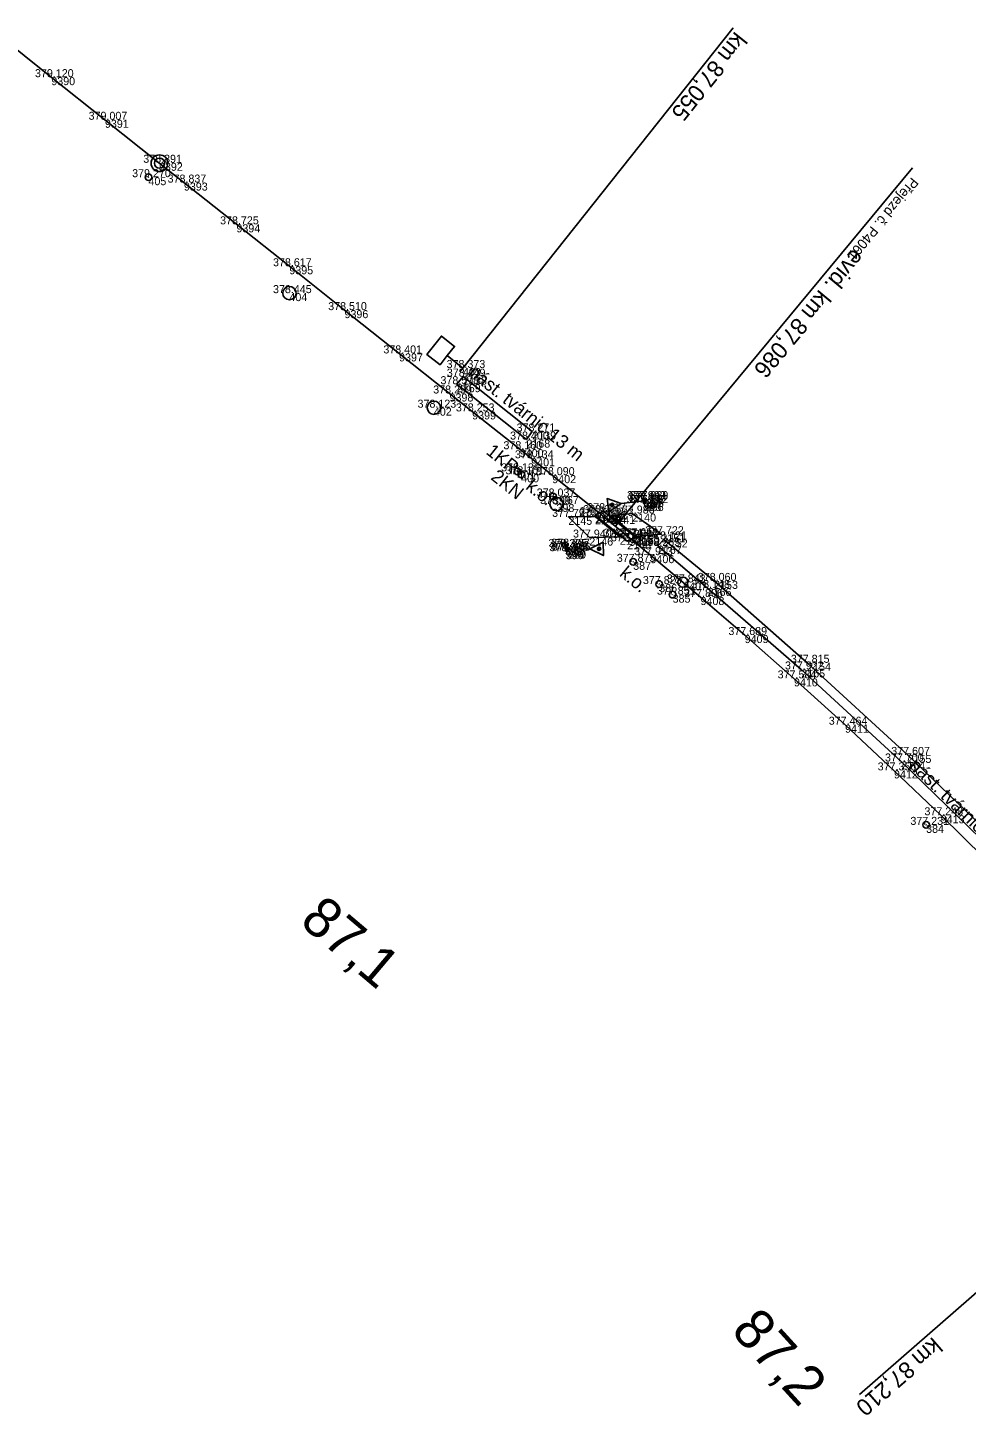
# Model space of a CAD drawing. Extents: x -599511 to -595511, y -1067427 to -1062061.
# Drawn here: x -596866.3 to -596725.5, y -1065469.6 to -1065261.5 of the extents above; entities that cross this region are included whole.
import ezdxf

# ---------------------------------------------------------------- set-up
doc = ezdxf.new("R2010")
doc.units = 0
for name, color, linetype in [('Vrstva 1', 7, 'Continuous'), ('Vrstva 12', 7, 'Continuous'), ('Vrstva 14', 7, 'Continuous'), ('Vrstva 27', 7, 'Continuous'), ('Vrstva 4', 7, 'Continuous'), ('Vrstva 43', 7, 'Continuous'), ('Vrstva 50', 7, 'Continuous'), ('Vrstva 60', 7, 'Continuous'), ('Vrstva 61', 7, 'Continuous'), ('Vrstva 7', 7, 'Continuous')]:
    doc.layers.add(name, color=color, linetype=linetype)

msp = doc.modelspace()

# ---------------------------------------------------------------- linework, layer by layer
at = {"layer": 'Vrstva 1'}
msp.add_lwpolyline([(-596870.95, -1065262.4), (-596862.77, -1065268.89), (-596854.72, -1065275.28), (-596846.61, -1065281.73), (-596842.87, -1065284.7), (-596834.99, -1065290.96), (-596827.05, -1065297.25), (-596818.77, -1065303.83), (-596810.58, -1065310.32), (-596803.01, -1065316.33), (-596799.61, -1065319.02), (-596792.47, -1065324.69), (-596790.75, -1065326.05), (-596787.59, -1065328.58), (-596780.52, -1065334.28), (-596780.05, -1065334.66), (-596775.99, -1065337.98), (-596772.85, -1065340.58), (-596767.94, -1065344.67), (-596765.34, -1065346.86), (-596758.71, -1065352.56), (-596751.32, -1065359.06), (-596743.65, -1065366.01), (-596736.31, -1065372.86), (-596729.29, -1065379.59), (-596722.75, -1065386.03)], dxfattribs=at)
at = {"layer": 'Vrstva 12'}
for points in [[(-596773.92, -1065332.17), (-596773.93, -1065332.76), (-596773.55, -1065332.77), (-596773.53, -1065332.18)], [(-596785.69, -1065339.35), (-596785.3, -1065339.31), (-596785.19, -1065339.89), (-596785.57, -1065339.98)]]:
    msp.add_lwpolyline(points, close=True, dxfattribs=at)
at = {"layer": 'Vrstva 14'}
msp.add_lwpolyline([(-596790.59, -1065322.03), (-596791.47, -1065323.24), (-596801.91, -1065314.94), (-596800.97, -1065313.8)], close=True, dxfattribs=at)
msp.add_lwpolyline([(-596688.36, -1065420.16), (-596688.18, -1065420.03), (-596687.53, -1065420.8), (-596687.34, -1065420.62), (-596688.01, -1065419.84), (-596687.33, -1065419.23), (-596705.98, -1065398.67), (-596706.41, -1065398.26), (-596706.92, -1065397.78), (-596720.57, -1065383.66), (-596734.27, -1065370.54), (-596749.34, -1065356.72), (-596763.3, -1065344.44), (-596770.84, -1065338.22), (-596771.74, -1065339.2), (-596764.28, -1065345.51), (-596750.22, -1065357.72), (-596735.21, -1065371.52), (-596721.61, -1065384.72), (-596707.91, -1065398.76), (-596707.49, -1065399.19), (-596707.13, -1065399.59), (-596688.36, -1065420.16)], dxfattribs=at)
at = {"layer": 'Vrstva 27'}
for p, q in [((-596792.86, -1065327.97), (-596792.78, -1065328.04)), ((-596792.3, -1065328.42), (-596792.22, -1065328.48)), ((-596787.51, -1065331.75), (-596787.44, -1065331.81)), ((-596775.49, -1065341.54), (-596775.41, -1065341.61))]:
    msp.add_line(p, q, dxfattribs=at)
for centre in [(-596792.82, -1065328.01), (-596792.26, -1065328.45), (-596787.48, -1065331.78), (-596775.45, -1065341.58)]:
    msp.add_circle(centre, 0.5, dxfattribs=at)
at = {"layer": 'Vrstva 4'}
for p, q in [((-596778.12, -1065336.23), (-596733.55, -1065282.5)), ((-596773.7, -1065333.21), (-596773.89, -1065331.66)), ((-596778.4, -1065333.2), (-596778.79, -1065332.9)), ((-596785.42, -1065338.91), (-596785.41, -1065340.46)), ((-596780.74, -1065339.43), (-596780.4, -1065339.78))]:
    msp.add_line(p, q, dxfattribs=at)
for points in [[(-596773.79, -1065332.43), (-596777.25, -1065332.85), (-596779.12, -1065334.08), (-596779.36, -1065332.09), (-596777.25, -1065332.85)], [(-596785.41, -1065339.69), (-596781.94, -1065339.65), (-596779.94, -1065338.64), (-596779.91, -1065340.64), (-596781.94, -1065339.65)]]:
    msp.add_lwpolyline(points, dxfattribs=at)
for points in [[(-596777.45, -1065337.81), (-596781.17, -1065334.77), (-596785.17, -1065334.83), (-596782.03, -1065337.94)], [(-596775.07, -1065337.93), (-596779.89, -1065333.98), (-596781.14, -1065334.59), (-596776.34, -1065338.5)], [(-596771.21, -1065337.44), (-596775.59, -1065334.34), (-596778.73, -1065334.7), (-596775.04, -1065337.74)]]:
    msp.add_lwpolyline(points, close=True, dxfattribs=at)
for centre in [(-596778.59, -1065333.05), (-596780.57, -1065339.61)]:
    msp.add_circle(centre, 0.248, dxfattribs=at)
at = {"layer": 'Vrstva 43'}
for centre in [(-596827.04, -1065301.28), (-596805.36, -1065318.46), (-596786.96, -1065332.91)]:
    msp.add_circle(centre, 1, dxfattribs=at)
at = {"layer": 'Vrstva 50'}
for p, q in [((-596771.58, -1065344.88), (-596771.5, -1065344.94)), ((-596731.53, -1065381), (-596731.45, -1065381.07))]:
    msp.add_line(p, q, dxfattribs=at)
for centre in [(-596771.54, -1065344.91), (-596731.49, -1065381.03)]:
    msp.add_circle(centre, 0.5, dxfattribs=at)
at = {"layer": 'Vrstva 60'}
for p, q in [((-596862.77, -1065268.89), (-596862.77, -1065268.89)), ((-596854.72, -1065275.28), (-596854.72, -1065275.28)), ((-596846.61, -1065281.73), (-596846.61, -1065281.73)), ((-596848.19, -1065283.89), (-596848.19, -1065283.89)), ((-596842.87, -1065284.7), (-596842.87, -1065284.7)), ((-596834.99, -1065290.96), (-596834.99, -1065290.96)), ((-596827.05, -1065297.25), (-596827.05, -1065297.25)), ((-596827.04, -1065301.28), (-596827.04, -1065301.28)), ((-596818.77, -1065303.83), (-596818.77, -1065303.83)), ((-596810.58, -1065310.32), (-596810.58, -1065310.32)), ((-596801, -1065312.51), (-596801, -1065312.51)), ((-596800.97, -1065313.8), (-596800.97, -1065313.8)), ((-596801.91, -1065314.94), (-596801.91, -1065314.94)), ((-596803.01, -1065316.33), (-596803.01, -1065316.33)), ((-596805.36, -1065318.46), (-596805.36, -1065318.46)), ((-596799.61, -1065319.02), (-596799.61, -1065319.02)), ((-596790.59, -1065322.03), (-596790.59, -1065322.03)), ((-596791.47, -1065323.24), (-596791.47, -1065323.24)), ((-596792.47, -1065324.69), (-596792.47, -1065324.69)), ((-596790.75, -1065326.05), (-596790.75, -1065326.05)), ((-596792.82, -1065328.01), (-596792.82, -1065328.01)), ((-596792.26, -1065328.45), (-596792.26, -1065328.45)), ((-596787.59, -1065328.58), (-596787.59, -1065328.58)), ((-596787.48, -1065331.78), (-596787.48, -1065331.78)), ((-596773.93, -1065332.76), (-596773.93, -1065332.76)), ((-596773.92, -1065332.17), (-596773.92, -1065332.17)), ((-596773.79, -1065332.43), (-596773.79, -1065332.43)), ((-596773.55, -1065332.77), (-596773.55, -1065332.77)), ((-596773.53, -1065332.18), (-596773.53, -1065332.18)), ((-596786.96, -1065332.91), (-596786.96, -1065332.91)), ((-596785.17, -1065334.83), (-596785.17, -1065334.83)), ((-596781.17, -1065334.77), (-596781.17, -1065334.77)), ((-596781.14, -1065334.59), (-596781.14, -1065334.59)), ((-596780.52, -1065334.28), (-596780.52, -1065334.28)), ((-596780.05, -1065334.66), (-596780.05, -1065334.66)), ((-596779.89, -1065333.98), (-596779.89, -1065333.98)), ((-596778.73, -1065334.7), (-596778.73, -1065334.7)), ((-596775.59, -1065334.34), (-596775.59, -1065334.34)), ((-596782.03, -1065337.94), (-596782.03, -1065337.94)), ((-596777.45, -1065337.81), (-596777.45, -1065337.81)), ((-596776.34, -1065338.5), (-596776.34, -1065338.5)), ((-596775.99, -1065337.98), (-596775.99, -1065337.98)), ((-596775.07, -1065337.93), (-596775.07, -1065337.93)), ((-596775.04, -1065337.74), (-596775.04, -1065337.74)), ((-596771.21, -1065337.44), (-596771.21, -1065337.44)), ((-596770.84, -1065338.22), (-596770.84, -1065338.22)), ((-596785.69, -1065339.35), (-596785.69, -1065339.35)), ((-596785.57, -1065339.98), (-596785.57, -1065339.98)), ((-596785.41, -1065339.69), (-596785.41, -1065339.69)), ((-596785.3, -1065339.31), (-596785.3, -1065339.31)), ((-596785.19, -1065339.89), (-596785.19, -1065339.89)), ((-596772.85, -1065340.58), (-596772.85, -1065340.58)), ((-596771.74, -1065339.2), (-596771.74, -1065339.2)), ((-596775.45, -1065341.58), (-596775.45, -1065341.58)), ((-596771.54, -1065344.91), (-596771.54, -1065344.91)), ((-596767.94, -1065344.67), (-596767.94, -1065344.67)), ((-596763.3, -1065344.44), (-596763.3, -1065344.44)), ((-596769.53, -1065346.5), (-596769.53, -1065346.5)), ((-596765.34, -1065346.86), (-596765.34, -1065346.86)), ((-596764.28, -1065345.51), (-596764.28, -1065345.51)), ((-596758.71, -1065352.56), (-596758.71, -1065352.56)), ((-596750.22, -1065357.72), (-596750.22, -1065357.72)), ((-596749.34, -1065356.72), (-596749.34, -1065356.72)), ((-596751.32, -1065359.06), (-596751.32, -1065359.06)), ((-596743.65, -1065366.01), (-596743.65, -1065366.01)), ((-596735.21, -1065371.52), (-596735.21, -1065371.52)), ((-596734.27, -1065370.54), (-596734.27, -1065370.54)), ((-596736.31, -1065372.86), (-596736.31, -1065372.86)), ((-596729.29, -1065379.59), (-596729.29, -1065379.59)), ((-596731.49, -1065381.03), (-596731.49, -1065381.03))]:
    msp.add_line(p, q, dxfattribs=at)
at = {"layer": 'Vrstva 7'}
for p, q in [((-596801, -1065312.51), (-596760.44, -1065261.48)), ((-596848.23, -1065283.86), (-596848.15, -1065283.92)), ((-596801.47, -1065313.1), (-596800.53, -1065311.92)), ((-596769.57, -1065346.47), (-596769.49, -1065346.53)), ((-596691.76, -1065423.11), (-596741.47, -1065466.46))]:
    msp.add_line(p, q, dxfattribs=at)
msp.add_lwpolyline([(-596801, -1065312.51), (-596803.35, -1065310.64), (-596802.26, -1065309.27), (-596804.22, -1065307.72), (-596806.4, -1065310.46), (-596804.44, -1065312.02), (-596803.35, -1065310.64)], dxfattribs=at)
for centre, radius in [((-596846.54, -1065281.79), 1.25), ((-596846.54, -1065281.79), 0.752), ((-596848.19, -1065283.89), 0.5), ((-596767.99, -1065344.63), 0.75), ((-596769.53, -1065346.5), 0.5)]:
    msp.add_circle(centre, radius, dxfattribs=at)

# ---------------------------------------------------------------- texts
at = {"layer": 'Vrstva 14'}
for s, rotation, p in [('nást. tvárnic 13 m', 321.5713, (-596800.33, -1065313.49)), ('nást. tvárnic. 116 m', 315.8636, (-596734.15, -1065372.31))]:
    msp.add_text(s, height=2, rotation=rotation, dxfattribs=at).set_placement(p)
at = {"layer": 'Vrstva 27'}
for s, rotation, p in [('1KR', 321.3579, (-596797.66, -1065325.29)), ('2KN', 321.3579, (-596796.95, -1065329.11)), ('k.o.', 321.1657, (-596791.71, -1065330.56)), ('k.o.', 320.4752, (-596777.63, -1065343.58))]:
    msp.add_text(s, height=2, rotation=rotation, dxfattribs=at).set_placement(p)
at = {"layer": 'Vrstva 4'}
for s, height, p in [('Přejezd č. P4061', 1.5, (-596733.66, -1065283.81)), ('evid. km 87,086', 2.5, (-596742.42, -1065294.47))]:
    msp.add_text(s, height=height, rotation=230.3233, dxfattribs=at).set_placement(p)
at = {"layer": 'Vrstva 60'}
for s, p in [('9390', (-596862.77, -1065270.09)), ('9391', (-596854.72, -1065276.48)), ('9392', (-596846.61, -1065282.93)), ('405', (-596848.19, -1065285.09)), ('9393', (-596842.87, -1065285.9)), ('9394', (-596834.99, -1065292.16)), ('9395', (-596827.05, -1065298.45)), ('404', (-596827.04, -1065302.48)), ('9396', (-596818.77, -1065305.03)), ('9397', (-596810.58, -1065311.52)), ('403', (-596801, -1065313.71)), ('2138', (-596800.97, -1065315)), ('2169', (-596801.91, -1065316.14)), ('9398', (-596803.01, -1065317.53)), ('402', (-596805.36, -1065319.66)), ('9399', (-596799.61, -1065320.22)), ('2139', (-596790.59, -1065323.23)), ('2168', (-596791.47, -1065324.44)), ('9400', (-596792.47, -1065325.89)), ('9401', (-596790.75, -1065327.25)), ('401', (-596792.82, -1065329.21)), ('400', (-596792.26, -1065329.65)), ('9402', (-596787.59, -1065329.78)), ('399', (-596787.48, -1065332.98)), ('393', (-596773.93, -1065333.96)), ('394', (-596773.92, -1065333.37)), ('397', (-596773.79, -1065333.63)), ('396', (-596773.55, -1065333.97)), ('395', (-596773.53, -1065333.38)), ('398', (-596786.96, -1065334.11)), ('2145', (-596785.17, -1065336.03)), ('2144', (-596781.17, -1065335.97)), ('2143', (-596781.14, -1065335.79)), ('9403', (-596780.52, -1065335.48)), ('9404', (-596780.05, -1065335.86)), ('2142', (-596779.89, -1065335.18)), ('2141', (-596778.73, -1065335.9)), ('2140', (-596775.59, -1065335.54)), ('2146', (-596782.03, -1065339.14)), ('2147', (-596777.45, -1065339.01)), ('2148', (-596776.34, -1065339.7)), ('9405', (-596775.99, -1065339.18)), ('2149', (-596775.07, -1065339.13)), ('2150', (-596775.04, -1065338.94)), ('2151', (-596771.21, -1065338.64)), ('2152', (-596770.84, -1065339.42)), ('391', (-596785.69, -1065340.55)), ('390', (-596785.57, -1065341.18)), ('392', (-596785.41, -1065340.89)), ('388', (-596785.3, -1065340.51)), ('389', (-596785.19, -1065341.09)), ('9406', (-596772.85, -1065341.78)), ('2167', (-596771.74, -1065340.4)), ('387', (-596775.45, -1065342.78)), ('386', (-596771.54, -1065346.11)), ('9407', (-596767.94, -1065345.87)), ('2153', (-596763.3, -1065345.64)), ('385', (-596769.53, -1065347.7)), ('9408', (-596765.34, -1065348.06)), ('2166', (-596764.28, -1065346.71)), ('9409', (-596758.71, -1065353.76)), ('2165', (-596750.22, -1065358.92)), ('2154', (-596749.34, -1065357.92)), ('9410', (-596751.32, -1065360.26)), ('9411', (-596743.65, -1065367.21)), ('2164', (-596735.21, -1065372.72)), ('2155', (-596734.27, -1065371.74)), ('9412', (-596736.31, -1065374.06)), ('9413', (-596729.29, -1065380.79)), ('384', (-596731.49, -1065382.23))]:
    msp.add_text(s, height=1.2, dxfattribs=at).set_placement(p)
at = {"layer": 'Vrstva 61'}
for s, p in [('379.120', (-596865.22, -1065268.89)), ('379.007', (-596857.17, -1065275.28)), ('378.891', (-596848.97, -1065281.73)), ('379.270', (-596850.64, -1065283.89)), ('378.837', (-596845.32, -1065284.7)), ('378.725', (-596837.44, -1065290.96)), ('378.617', (-596829.5, -1065297.25)), ('378.445', (-596829.5, -1065301.28)), ('378.510', (-596821.22, -1065303.83)), ('378.401', (-596812.94, -1065310.32)), ('378.373', (-596803.45, -1065312.51)), ('378.578', (-596804.37, -1065314.94)), ('378.449', (-596803.42, -1065313.8)), ('378.299', (-596805.46, -1065316.33)), ('378.123', (-596807.81, -1065318.46)), ('378.253', (-596802.06, -1065319.02)), ('378.400', (-596793.92, -1065323.24)), ('378.271', (-596792.95, -1065322.03)), ('378.160', (-596794.92, -1065324.69)), ('378.134', (-596793.2, -1065326.05)), ('378.134', (-596795.27, -1065328.01)), ('378.101', (-596794.62, -1065328.45)), ('378.090', (-596790.04, -1065328.58)), ('378.037', (-596789.93, -1065331.78)), ('378.067', (-596789.42, -1065332.91)), ('378.017', (-596782.34, -1065333.98)), ('377.997', (-596776.39, -1065332.76)), ('377.992', (-596776.37, -1065332.17)), ('377.994', (-596776.24, -1065332.43)), ('377.992', (-596775.99, -1065332.77)), ('377.989', (-596775.98, -1065332.18)), ('377.797', (-596787.62, -1065334.83)), ('378.001', (-596783.53, -1065334.77)), ('378.011', (-596783.49, -1065334.59)), ('378.008', (-596782.97, -1065334.28)), ('378.007', (-596782.5, -1065334.66)), ('378.003', (-596781.18, -1065334.7)), ('377.986', (-596778.04, -1065334.34)), ('377.940', (-596784.48, -1065337.94)), ('377.974', (-596779.9, -1065337.81)), ('377.967', (-596778.44, -1065337.98)), ('377.967', (-596777.52, -1065337.93)), ('377.958', (-596777.49, -1065337.74)), ('377.722', (-596773.66, -1065337.44)), ('378.305', (-596788.15, -1065339.35)), ('378.305', (-596788.02, -1065339.98)), ('378.328', (-596787.87, -1065339.69)), ('378.307', (-596787.75, -1065339.31)), ('378.306', (-596787.64, -1065339.89)), ('377.964', (-596778.8, -1065338.5)), ('378.265', (-596774.2, -1065339.2)), ('378.121', (-596773.2, -1065338.22)), ('377.875', (-596777.91, -1065341.58)), ('377.913', (-596775.3, -1065340.58)), ('377.823', (-596773.99, -1065344.91)), ('377.843', (-596770.39, -1065344.67)), ('378.148', (-596766.73, -1065345.51)), ('378.060', (-596765.75, -1065344.44)), ('377.851', (-596771.89, -1065346.5)), ('377.806', (-596767.79, -1065346.86)), ('377.689', (-596761.16, -1065352.56)), ('377.815', (-596751.79, -1065356.72)), ('377.922', (-596752.67, -1065357.72)), ('377.584', (-596753.77, -1065359.06)), ('377.464', (-596746.1, -1065366.01)), ('377.607', (-596736.72, -1065370.54)), ('377.356', (-596738.76, -1065372.86)), ('377.700', (-596737.66, -1065371.52)), ('377.248', (-596731.74, -1065379.59)), ('377.231', (-596733.85, -1065381.03))]:
    msp.add_text(s, height=1.2, dxfattribs=at).set_placement(p)
at = {"layer": 'Vrstva 7'}
for s, height, rotation, p in [('km 87,055', 2.5, 231.5226, (-596760.15, -1065261.92)), ('87,1', 6, 319.8042, (-596825.69, -1065395.81)), ('87,2', 6, 312.3493, (-596760.93, -1065457.01)), ('km 87,210', 2.5, 221.089, (-596730.48, -1065457.74))]:
    msp.add_text(s, height=height, rotation=rotation, dxfattribs=at).set_placement(p)

doc.saveas('drawing.dxf')
